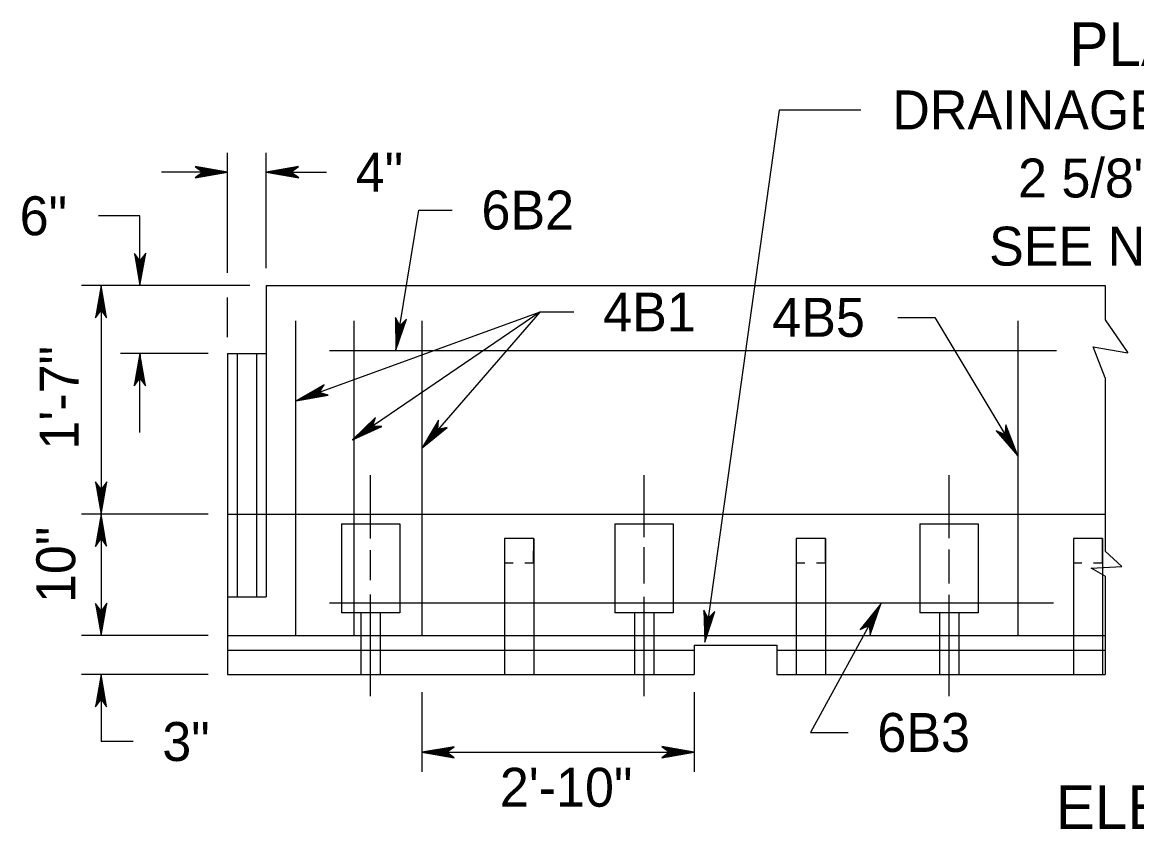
# Model space of a CAD drawing. Extents: x 499883 to 500983, y 499104 to 499764.
# Drawn here: x 500279.7 to 500394.2, y 499232.3 to 499315.2 of the extents above; entities that cross this region are included whole.
import ezdxf

# ---------------------------------------------------------------- set-up
doc = ezdxf.new("R2010")
doc.units = 0
for name, color, linetype in [('1', 7, 'Continuous'), ('24', 7, 'Continuous'), ('3', 7, 'Continuous'), ('5', 7, 'Continuous')]:
    doc.layers.add(name, color=color, linetype=linetype)

msp = doc.modelspace()

# ---------------------------------------------------------------- linework, layer by layer
at = {"layer": '1'}
for p, q in [((500315.49, 499262.18), (500315.49, 499268.7)), ((500343.61, 499262.32), (500343.61, 499268.7)), ((500374.95, 499262.22), (500374.95, 499268.7)), ((500315.49, 499257.89), (500315.49, 499260.99)), ((500343.61, 499257.57), (500343.61, 499261.31)), ((500374.95, 499257.57), (500374.95, 499261.04)), ((500315.49, 499245.98), (500315.49, 499256.43)), ((500343.61, 499245.98), (500343.61, 499256.2)), ((500374.95, 499245.98), (500374.95, 499256.39))]:
    msp.add_line(p, q, dxfattribs=at)
at = {"layer": '24'}
for points in [[(500318.08, 499281.55), (500320.45, 499295.94), (500323.89, 499295.94)], [(500318.08, 499281.55), (500319.2, 499284.73), (500318.49, 499284.05), (500318.05, 499284.91), (500318.08, 499281.55), (500318.11, 499281.77), (500319.14, 499284.65), (500318.48, 499283.99), (500318.07, 499284.77), (500318.12, 499281.89), (500318.16, 499281.99), (500319.03, 499284.46), (500318.47, 499283.97), (500318.12, 499284.63), (500318.16, 499282.04), (500318.17, 499282.16), (500318.93, 499284.31), (500318.48, 499283.95), (500318.15, 499284.45), (500318.22, 499282.47), (500318.25, 499282.66), (500318.82, 499284.16), (500318.48, 499283.91), (500318.21, 499284.29), (500318.27, 499282.69), (500318.31, 499282.86), (500318.7, 499284), (500318.44, 499283.81), (500318.25, 499284.09), (500318.32, 499283.02), (500318.37, 499283.19), (500318.62, 499283.87), (500318.44, 499283.78), (500318.3, 499284), (500318.37, 499283.28), (500318.55, 499283.72), (500318.41, 499283.67), (500318.32, 499283.89), (500318.37, 499283.39), (500318.49, 499283.68), (500318.37, 499283.57), (500318.34, 499283.73), (500318.41, 499283.57), (500318.44, 499283.64)], [(500307.86, 499276.34), (500311.14, 499276.92), (500310.2, 499277.2), (500310.73, 499277.99), (500307.86, 499276.34), (500308.06, 499276.42), (500311.03, 499276.93), (500310.14, 499277.18), (500310.62, 499277.91), (500308.17, 499276.47), (500308.28, 499276.49), (500310.82, 499276.94), (500310.13, 499277.18), (500310.53, 499277.79), (500308.33, 499276.51), (500308.42, 499276.56), (500310.64, 499276.95), (500310.11, 499277.16), (500310.38, 499277.69), (500308.72, 499276.67), (500308.89, 499276.74), (500310.46, 499276.97), (500310.08, 499277.14), (500310.27, 499277.56), (500308.93, 499276.73), (500309.1, 499276.78), (500310.26, 499276.99), (500309.97, 499277.13), (500310.13, 499277.42), (500309.24, 499276.85), (500309.4, 499276.89), (500310.11, 499277), (500309.95, 499277.11), (500310.07, 499277.34), (500309.48, 499276.93), (500309.95, 499276.99), (500309.84, 499277.08), (500309.99, 499277.27), (500309.58, 499276.99), (500309.89, 499277.02), (500309.74, 499277.07), (500309.85, 499277.17), (500309.75, 499277.04), (500309.83, 499277.05)], [(500313.63, 499272.31), (500316.66, 499273.68), (500315.69, 499273.71), (500316, 499274.62), (500313.63, 499272.31), (500313.81, 499272.44), (500316.56, 499273.66), (500315.64, 499273.69), (500315.92, 499274.5), (500313.9, 499272.51), (500314, 499272.56), (500316.35, 499273.62), (500315.62, 499273.68), (500315.86, 499274.37), (500314.04, 499272.59), (500314.12, 499272.66), (500316.18, 499273.58), (500315.61, 499273.66), (500315.75, 499274.24), (500314.38, 499272.84), (500314.54, 499272.94), (500316, 499273.56), (500315.58, 499273.63), (500315.67, 499274.08), (500314.57, 499272.95), (500314.72, 499273.04), (500315.8, 499273.53), (500315.49, 499273.59), (500315.56, 499273.92), (500314.85, 499273.14), (500314.99, 499273.22), (500315.65, 499273.5), (500315.47, 499273.57), (500315.52, 499273.82), (500315.06, 499273.28), (500315.49, 499273.45), (500315.37, 499273.51), (500315.46, 499273.73), (500315.14, 499273.36), (500315.43, 499273.47), (500315.27, 499273.48), (500315.36, 499273.61), (500315.29, 499273.45), (500315.36, 499273.48)], [(500313.63, 499272.31), (500316.66, 499273.68), (500315.69, 499273.71), (500316, 499274.62), (500313.63, 499272.31), (500313.81, 499272.44), (500316.56, 499273.66), (500315.64, 499273.69), (500315.92, 499274.5), (500313.9, 499272.51), (500314, 499272.56), (500316.35, 499273.62), (500315.62, 499273.68), (500315.86, 499274.37), (500314.04, 499272.59), (500314.12, 499272.66), (500316.18, 499273.58), (500315.61, 499273.66), (500315.75, 499274.24), (500314.38, 499272.84), (500314.54, 499272.94), (500316, 499273.56), (500315.58, 499273.63), (500315.67, 499274.08), (500314.57, 499272.95), (500314.72, 499273.04), (500315.8, 499273.53), (500315.49, 499273.59), (500315.56, 499273.92), (500314.85, 499273.14), (500314.99, 499273.22), (500315.65, 499273.5), (500315.47, 499273.57), (500315.52, 499273.82), (500315.06, 499273.28), (500315.49, 499273.45), (500315.37, 499273.51), (500315.46, 499273.73), (500315.14, 499273.36), (500315.43, 499273.47), (500315.27, 499273.48), (500315.36, 499273.61), (500315.29, 499273.45), (500315.36, 499273.48)], [(500320.78, 499271.5), (500323.36, 499273.59), (500322.41, 499273.38), (500322.49, 499274.33), (500320.78, 499271.5), (500320.92, 499271.67), (500323.27, 499273.55), (500322.37, 499273.34), (500322.43, 499274.21), (500320.99, 499271.77), (500321.07, 499271.84), (500323.08, 499273.46), (500322.36, 499273.33), (500322.41, 499274.06), (500321.1, 499271.87), (500321.16, 499271.97), (500322.92, 499273.38), (500322.35, 499273.31), (500322.34, 499273.9), (500321.37, 499272.21), (500321.49, 499272.35), (500322.75, 499273.31), (500322.33, 499273.27), (500322.3, 499273.73), (500321.53, 499272.36), (500321.65, 499272.49), (500322.56, 499273.24), (500322.25, 499273.22), (500322.24, 499273.55), (500321.74, 499272.61), (500321.87, 499272.73), (500322.43, 499273.17), (500322.23, 499273.19), (500322.23, 499273.44), (500321.91, 499272.8), (500322.29, 499273.08), (500322.15, 499273.11), (500322.19, 499273.34), (500321.97, 499272.9), (500322.23, 499273.08), (500322.07, 499273.05), (500322.12, 499273.2), (500322.09, 499273.03), (500322.16, 499273.07)], [(500382, 499270.68), (500380.79, 499273.86), (500380.69, 499272.87), (500379.79, 499273.24), (500382, 499270.68), (500381.88, 499270.87), (500380.8, 499273.75), (500380.72, 499272.81), (500379.9, 499273.15), (500381.81, 499270.96), (500381.77, 499271.07), (500380.83, 499273.53), (500380.73, 499272.79), (500380.03, 499273.07), (500381.74, 499271.11), (500381.67, 499271.2), (500380.86, 499273.36), (500380.75, 499272.78), (500380.17, 499272.95), (500381.51, 499271.48), (500381.41, 499271.64), (500380.87, 499273.17), (500380.77, 499272.75), (500380.32, 499272.87), (500381.41, 499271.68), (500381.32, 499271.83), (500380.89, 499272.97), (500380.8, 499272.65), (500380.48, 499272.75), (500381.23, 499271.97), (500381.16, 499272.12), (500380.91, 499272.81), (500380.83, 499272.63), (500380.58, 499272.7), (500381.1, 499272.19), (500380.95, 499272.65), (500380.88, 499272.53), (500380.66, 499272.64), (500381.02, 499272.28), (500380.93, 499272.59), (500380.91, 499272.42), (500380.78, 499272.52), (500380.94, 499272.44), (500380.92, 499272.52)], [(500367.93, 499255.48), (500360.71, 499242.25), (500364.58, 499242.25)], [(500367.93, 499255.48), (500365.82, 499252.84), (500366.72, 499253.26), (500366.85, 499252.3), (500367.93, 499255.48), (500367.83, 499255.28), (500365.9, 499252.9), (500366.75, 499253.31), (500366.88, 499252.44), (500367.78, 499255.17), (500367.71, 499255.08), (500366.08, 499253.04), (500366.76, 499253.32), (500366.87, 499252.59), (500367.69, 499255.04), (500367.65, 499254.93), (500366.21, 499253.15), (500366.77, 499253.35), (500366.91, 499252.76), (500367.5, 499254.65), (500367.41, 499254.49), (500366.37, 499253.26), (500366.78, 499253.38), (500366.91, 499252.94), (500367.38, 499254.47), (500367.28, 499254.31), (500366.54, 499253.37), (500366.85, 499253.46), (500366.93, 499253.13), (500367.21, 499254.17), (500367.12, 499254.03), (500366.66, 499253.47), (500366.85, 499253.49), (500366.92, 499253.24), (500367.09, 499253.94), (500366.77, 499253.59), (500366.92, 499253.59), (500366.93, 499253.35), (500367.05, 499253.83), (500366.84, 499253.6), (500366.99, 499253.67), (500366.97, 499253.51), (500366.96, 499253.68), (500366.91, 499253.62)], [(500349.85, 499251.52), (500350.88, 499254.68), (500350.2, 499253.98), (500349.74, 499254.82), (500349.85, 499251.52), (500349.87, 499251.73), (500350.82, 499254.59), (500350.18, 499253.92), (500349.76, 499254.68), (500349.88, 499251.85), (500349.91, 499251.96), (500350.71, 499254.41), (500350.18, 499253.91), (500349.82, 499254.55), (500349.92, 499252), (500349.92, 499252.11), (500350.62, 499254.26), (500350.18, 499253.88), (500349.85, 499254.38), (500349.96, 499252.43), (500349.99, 499252.61), (500350.52, 499254.11), (500350.19, 499253.85), (500349.91, 499254.22), (500350.01, 499252.64), (500350.04, 499252.81), (500350.4, 499253.94), (500350.15, 499253.75), (500349.96, 499254.02), (500350.05, 499252.97), (500350.09, 499253.13), (500350.32, 499253.81), (500350.15, 499253.72), (500350, 499253.93), (500350.09, 499253.22), (500350.26, 499253.66), (500350.13, 499253.61), (500350.03, 499253.83), (500350.09, 499253.34), (500350.2, 499253.62), (500350.09, 499253.51), (500350.05, 499253.67), (500350.12, 499253.51), (500350.15, 499253.58)], [(500320.76, 499240.21), (500324.09, 499239.63), (500323.29, 499240.21), (500324.07, 499240.79), (500320.76, 499240.21), (500320.99, 499240.22), (500324, 499239.67), (500323.23, 499240.22), (500323.94, 499240.75), (500321.1, 499240.23), (500321.22, 499240.21), (500323.79, 499239.76), (500323.22, 499240.22), (500323.81, 499240.67), (500321.27, 499240.21), (500321.38, 499240.23), (500323.63, 499239.82), (500323.19, 499240.21), (500323.64, 499240.62), (500321.7, 499240.23), (500321.88, 499240.23), (500323.46, 499239.91), (500323.16, 499240.2), (500323.49, 499240.53), (500321.92, 499240.21), (500322.1, 499240.2), (500323.28, 499240), (500323.05, 499240.23), (500323.3, 499240.46), (500322.26, 499240.21), (500322.43, 499240.2), (500323.14, 499240.06), (500323.02, 499240.22), (500323.22, 499240.4), (500322.51, 499240.21), (500322.98, 499240.1), (500322.91, 499240.23), (500323.11, 499240.36), (500322.63, 499240.23), (500322.93, 499240.15), (500322.81, 499240.25), (500322.95, 499240.31), (500322.81, 499240.22), (500322.88, 499240.2)], [(500348.75, 499240.21), (500345.43, 499240.8), (500346.22, 499240.21), (500345.44, 499239.64), (500348.75, 499240.21), (500348.53, 499240.21), (500345.52, 499240.76), (500346.28, 499240.21), (500345.58, 499239.68), (500348.41, 499240.2), (500348.3, 499240.21), (500345.72, 499240.67), (500346.3, 499240.21), (500345.7, 499239.76), (500348.25, 499240.21), (500348.14, 499240.2), (500345.88, 499240.6), (500346.32, 499240.21), (500345.88, 499239.81), (500347.82, 499240.2), (500347.63, 499240.2), (500346.05, 499240.52), (500346.36, 499240.22), (500346.03, 499239.89), (500347.6, 499240.21), (500347.42, 499240.22), (500346.23, 499240.43), (500346.46, 499240.2), (500346.21, 499239.97), (500347.26, 499240.21), (500347.09, 499240.23), (500346.38, 499240.37), (500346.49, 499240.21), (500346.3, 499240.03), (500347, 499240.21), (500346.54, 499240.32), (500346.6, 499240.2), (500346.4, 499240.07), (500346.88, 499240.2), (500346.58, 499240.27), (500346.71, 499240.17), (500346.56, 499240.11), (500346.71, 499240.21), (500346.63, 499240.22)]]:
    msp.add_lwpolyline(points, dxfattribs=at)
at = {"layer": '3'}
for points in [[(500329.26, 499262.2), (500329.26, 499259.68), (500330.14, 499259.69)], [(500331.34, 499259.69), (500332.25, 499259.69), (500332.26, 499262.2), (500329.26, 499262.2)], [(500359.24, 499262.2), (500359.24, 499259.68), (500360.12, 499259.69)], [(500361.32, 499259.69), (500362.24, 499259.69), (500362.24, 499262.2), (500359.24, 499262.2)], [(500387.72, 499262.2), (500387.72, 499259.68), (500388.6, 499259.69)], [(500389.8, 499259.69), (500390.71, 499259.69), (500390.72, 499262.2), (500387.72, 499262.2)]]:
    msp.add_lwpolyline(points, dxfattribs=at)
at = {"layer": '5'}
for p, q in [((500300.79, 499289.48), (500300.79, 499301.83)), ((500304.78, 499289.95), (500304.78, 499301.83)), ((500300.79, 499299.83), (500294.02, 499299.83)), ((500304.78, 499299.83), (500310.97, 499299.83)), ((500291.79, 499295.35), (500287.54, 499295.35)), ((500291.79, 499288.18), (500291.79, 499295.35)), ((500303.09, 499288.18), (500285.8, 499288.18)), ((500287.8, 499288.18), (500287.8, 499264.7)), ((500304.78, 499288.18), (500391, 499288.18)), ((500304.78, 499288.18), (500304.78, 499281.18)), ((500391, 499288.18), (500391, 499284.64)), ((500300.79, 499282.88), (500300.79, 499286.94)), ((500332.9, 499285.46), (500313.63, 499272.31)), ((500332.9, 499285.46), (500320.78, 499271.5)), ((500307.77, 499284.56), (500307.77, 499252.2)), ((500313.77, 499284.56), (500313.77, 499252.2)), ((500320.76, 499284.56), (500320.76, 499252.2)), ((500382, 499284.56), (500382, 499252.2)), ((500391, 499284.64), (500393.31, 499281.27)), ((500391, 499278.7), (500389.75, 499281.87)), ((500389.75, 499281.87), (500393.31, 499281.27)), ((500298.81, 499281.18), (500289.79, 499281.18)), ((500291.79, 499273.09), (500291.79, 499281.18)), ((500300.79, 499281.18), (500300.79, 499248.21)), ((500300.79, 499281.18), (500304.78, 499281.18)), ((500301.79, 499281.18), (500301.79, 499256.2)), ((500303.78, 499281.18), (500303.78, 499256.2)), ((500304.78, 499281.18), (500304.78, 499256.2)), ((500311.26, 499281.5), (500386, 499281.5)), ((500391, 499278.7), (500391, 499260.89)), ((500298.81, 499264.7), (500285.8, 499264.7)), ((500287.8, 499264.7), (500287.8, 499252.2)), ((500300.79, 499264.7), (500391, 499264.7)), ((500312.49, 499263.7), (500312.49, 499254.56)), ((500312.49, 499263.7), (500318.49, 499263.7)), ((500318.49, 499263.7), (500318.49, 499254.56)), ((500340.61, 499263.7), (500340.61, 499254.56)), ((500340.61, 499263.7), (500346.61, 499263.7)), ((500346.61, 499263.7), (500346.61, 499254.56)), ((500371.95, 499263.7), (500371.95, 499254.56)), ((500371.95, 499263.7), (500377.94, 499263.7)), ((500377.94, 499263.7), (500377.94, 499254.56)), ((500329.26, 499262.2), (500329.26, 499248.21)), ((500332.26, 499262.2), (500332.26, 499248.21)), ((500359.24, 499262.2), (500359.24, 499248.21)), ((500362.24, 499262.2), (500362.24, 499248.21)), ((500387.72, 499262.2), (500387.72, 499248.21)), ((500390.72, 499262.2), (500390.72, 499248.21)), ((500391, 499260.89), (500392.72, 499259.31)), ((500389.55, 499259.14), (500392.72, 499259.31)), ((500391, 499258.32), (500389.55, 499259.14)), ((500391, 499258.32), (500391, 499248.21)), ((500300.79, 499256.2), (500304.78, 499256.2)), ((500311.26, 499255.56), (500385.67, 499255.56)), ((500318.49, 499254.56), (500312.49, 499254.56)), ((500314.49, 499254.56), (500314.49, 499248.21)), ((500316.49, 499254.56), (500316.49, 499248.21)), ((500346.61, 499254.56), (500340.61, 499254.56)), ((500342.61, 499254.56), (500342.61, 499248.21)), ((500344.61, 499254.56), (500344.61, 499248.21)), ((500377.94, 499254.56), (500371.95, 499254.56)), ((500373.95, 499254.56), (500373.95, 499248.21)), ((500375.94, 499254.56), (500375.94, 499248.21)), ((500298.81, 499252.2), (500285.8, 499252.2)), ((500300.79, 499252.2), (500391, 499252.2)), ((500300.79, 499250.71), (500348.75, 499250.71)), ((500348.75, 499251.21), (500357.24, 499251.21)), ((500348.75, 499251.21), (500348.75, 499248.21)), ((500357.24, 499251.21), (500357.24, 499248.21)), ((500357.24, 499250.71), (500391, 499250.71)), ((500298.81, 499248.21), (500285.8, 499248.21)), ((500287.8, 499248.21), (500287.8, 499241.32)), ((500300.79, 499248.21), (500348.75, 499248.21)), ((500357.24, 499248.21), (500391, 499248.21)), ((500320.76, 499246.4), (500320.76, 499238.22)), ((500348.75, 499246.4), (500348.75, 499238.22)), ((500291.09, 499241.32), (500287.8, 499241.32)), ((500320.76, 499240.21), (500348.75, 499240.21))]:
    msp.add_line(p, q, dxfattribs=at)
for points in [[(500365.88, 499306.22), (500357.5, 499306.22), (500349.85, 499251.52)], [(500300.79, 499299.83), (500297.46, 499300.42), (500298.26, 499299.83), (500297.48, 499299.26), (500300.79, 499299.83), (500300.57, 499299.83), (500297.56, 499300.38), (500298.32, 499299.83), (500297.61, 499299.3), (500300.45, 499299.82), (500300.34, 499299.83), (500297.76, 499300.29), (500298.34, 499299.83), (500297.74, 499299.38), (500300.29, 499299.83), (500300.18, 499299.82), (500297.92, 499300.22), (500298.36, 499299.83), (500297.91, 499299.43), (500299.85, 499299.82), (500299.67, 499299.82), (500298.09, 499300.14), (500298.4, 499299.84), (500298.06, 499299.51), (500299.63, 499299.83), (500299.46, 499299.84), (500298.27, 499300.05), (500298.5, 499299.82), (500298.25, 499299.59), (500299.29, 499299.83), (500299.12, 499299.85), (500298.41, 499299.99), (500298.53, 499299.83), (500298.34, 499299.65), (500299.04, 499299.83), (500298.57, 499299.95), (500298.64, 499299.82), (500298.44, 499299.69), (500298.92, 499299.82), (500298.62, 499299.89), (500298.74, 499299.79), (500298.6, 499299.73), (500298.74, 499299.83), (500298.67, 499299.84)], [(500304.78, 499299.83), (500308.11, 499299.25), (500307.31, 499299.83), (500308.09, 499300.41), (500304.78, 499299.83), (500305, 499299.84), (500308.01, 499299.29), (500307.25, 499299.84), (500307.96, 499300.37), (500305.12, 499299.85), (500305.23, 499299.83), (500307.81, 499299.38), (500307.23, 499299.84), (500307.83, 499300.29), (500305.28, 499299.83), (500305.4, 499299.85), (500307.65, 499299.44), (500307.21, 499299.83), (500307.66, 499300.24), (500305.72, 499299.85), (500305.9, 499299.85), (500307.48, 499299.53), (500307.18, 499299.83), (500307.51, 499300.16), (500305.94, 499299.83), (500306.11, 499299.82), (500307.3, 499299.62), (500307.07, 499299.85), (500307.32, 499300.08), (500306.28, 499299.83), (500306.45, 499299.82), (500307.16, 499299.68), (500307.04, 499299.84), (500307.23, 499300.02), (500306.53, 499299.83), (500307, 499299.72), (500306.93, 499299.85), (500307.13, 499299.98), (500306.65, 499299.85), (500306.95, 499299.78), (500306.83, 499299.88), (500306.97, 499299.94), (500306.83, 499299.84), (500306.9, 499299.83)], [(500291.79, 499288.18), (500292.38, 499291.5), (500291.79, 499290.71), (500291.22, 499291.48), (500291.79, 499288.18), (500291.79, 499288.4), (500292.34, 499291.41), (500291.79, 499290.65), (500291.26, 499291.35), (500291.78, 499288.52), (500291.79, 499288.63), (500292.25, 499291.21), (500291.79, 499290.63), (500291.34, 499291.22), (500291.79, 499288.68), (500291.78, 499288.79), (500292.18, 499291.04), (500291.79, 499290.6), (500291.39, 499291.05), (500291.78, 499289.11), (500291.78, 499289.3), (500292.1, 499290.88), (500291.8, 499290.57), (500291.47, 499290.9), (500291.79, 499289.33), (500291.8, 499289.51), (500292.01, 499290.7), (500291.78, 499290.47), (500291.55, 499290.71), (500291.79, 499289.67), (500291.81, 499289.84), (500291.95, 499290.55), (500291.79, 499290.43), (500291.61, 499290.63), (500291.79, 499289.93), (500291.9, 499290.39), (500291.78, 499290.32), (500291.65, 499290.53), (500291.78, 499290.04), (500291.85, 499290.35), (500291.75, 499290.22), (500291.69, 499290.37), (500291.79, 499290.22), (500291.8, 499290.3)], [(500287.8, 499288.18), (500287.21, 499284.85), (500287.8, 499285.65), (500288.37, 499284.87), (500287.8, 499288.18), (500287.8, 499287.96), (500287.25, 499284.95), (500287.8, 499285.71), (500288.33, 499285), (500287.81, 499287.84), (500287.8, 499287.73), (500287.34, 499285.15), (500287.8, 499285.73), (500288.25, 499285.13), (500287.8, 499287.68), (500287.81, 499287.57), (500287.41, 499285.31), (500287.8, 499285.75), (500288.2, 499285.3), (500287.81, 499287.24), (500287.81, 499287.06), (500287.49, 499285.48), (500287.79, 499285.79), (500288.12, 499285.46), (500287.8, 499287.02), (500287.79, 499286.85), (500287.58, 499285.66), (500287.81, 499285.89), (500288.04, 499285.64), (500287.8, 499286.68), (500287.78, 499286.52), (500287.64, 499285.8), (500287.8, 499285.92), (500287.98, 499285.73), (500287.8, 499286.43), (500287.69, 499285.96), (500287.81, 499286.03), (500287.94, 499285.83), (500287.81, 499286.31), (500287.74, 499286.01), (500287.84, 499286.13), (500287.9, 499285.99), (500287.8, 499286.13), (500287.79, 499286.06)], [(500336.4, 499285.46), (500332.9, 499285.46), (500307.86, 499276.34)], [(500369.69, 499284.91), (500373.5, 499284.89), (500382, 499270.68)], [(500291.79, 499281.18), (500291.21, 499277.86), (500291.79, 499278.65), (500292.37, 499277.88), (500291.79, 499281.18), (500291.8, 499280.96), (500291.25, 499277.95), (500291.8, 499278.72), (500292.33, 499278.01), (500291.81, 499280.84), (500291.79, 499280.73), (500291.34, 499278.15), (500291.8, 499278.73), (500292.25, 499278.14), (500291.79, 499280.68), (500291.81, 499280.57), (500291.4, 499278.32), (500291.79, 499278.76), (500292.2, 499278.31), (500291.81, 499280.25), (500291.81, 499280.06), (500291.49, 499278.48), (500291.78, 499278.79), (500292.11, 499278.46), (500291.79, 499280.03), (500291.78, 499279.85), (500291.58, 499278.66), (500291.81, 499278.89), (500292.04, 499278.65), (500291.79, 499279.69), (500291.78, 499279.52), (500291.64, 499278.81), (500291.8, 499278.93), (500291.98, 499278.73), (500291.79, 499279.43), (500291.68, 499278.97), (500291.81, 499279.04), (500291.94, 499278.83), (500291.81, 499279.32), (500291.73, 499279.01), (500291.83, 499279.14), (500291.89, 499278.99), (500291.8, 499279.14), (500291.78, 499279.06)], [(500287.8, 499264.7), (500288.38, 499268.02), (500287.8, 499267.22), (500287.22, 499268), (500287.8, 499264.7), (500287.79, 499264.92), (500288.34, 499267.93), (500287.79, 499267.16), (500287.26, 499267.87), (500287.78, 499265.04), (500287.8, 499265.15), (500288.25, 499267.72), (500287.79, 499267.15), (500287.34, 499267.74), (500287.8, 499265.2), (500287.78, 499265.31), (500288.19, 499267.56), (500287.8, 499267.12), (500287.39, 499267.57), (500287.78, 499265.63), (500287.78, 499265.82), (500288.1, 499267.39), (500287.81, 499267.09), (500287.48, 499267.42), (500287.8, 499265.85), (500287.81, 499266.03), (500288.01, 499267.21), (500287.78, 499266.98), (500287.55, 499267.23), (500287.8, 499266.19), (500287.81, 499266.36), (500287.95, 499267.07), (500287.79, 499266.95), (500287.61, 499267.15), (500287.8, 499266.44), (500287.91, 499266.91), (500287.78, 499266.84), (500287.65, 499267.05), (500287.78, 499266.56), (500287.86, 499266.87), (500287.76, 499266.74), (500287.7, 499266.88), (500287.79, 499266.74), (500287.81, 499266.82)], [(500287.8, 499264.7), (500287.21, 499261.37), (500287.8, 499262.17), (500288.37, 499261.39), (500287.8, 499264.7), (500287.8, 499264.47), (500287.25, 499261.46), (500287.8, 499262.23), (500288.33, 499261.52), (500287.81, 499264.36), (500287.8, 499264.24), (500287.34, 499261.67), (500287.8, 499262.24), (500288.25, 499261.65), (500287.8, 499264.19), (500287.81, 499264.08), (500287.41, 499261.83), (500287.8, 499262.27), (500288.2, 499261.82), (500287.81, 499263.76), (500287.81, 499263.57), (500287.49, 499262), (500287.79, 499262.3), (500288.12, 499261.97), (500287.8, 499263.54), (500287.79, 499263.36), (500287.58, 499262.18), (500287.81, 499262.41), (500288.04, 499262.16), (500287.8, 499263.2), (500287.78, 499263.03), (500287.64, 499262.32), (500287.8, 499262.44), (500287.98, 499262.24), (500287.8, 499262.95), (500287.69, 499262.48), (500287.81, 499262.55), (500287.94, 499262.34), (500287.81, 499262.83), (500287.74, 499262.53), (500287.84, 499262.65), (500287.9, 499262.51), (500287.8, 499262.65), (500287.79, 499262.58)], [(500287.8, 499252.2), (500288.38, 499255.53), (500287.8, 499254.73), (500287.22, 499255.51), (500287.8, 499252.2), (500287.79, 499252.43), (500288.34, 499255.44), (500287.79, 499254.67), (500287.26, 499255.38), (500287.78, 499252.54), (500287.8, 499252.66), (500288.25, 499255.23), (500287.79, 499254.66), (500287.34, 499255.25), (500287.8, 499252.71), (500287.78, 499252.82), (500288.19, 499255.07), (500287.8, 499254.63), (500287.39, 499255.08), (500287.78, 499253.14), (500287.78, 499253.32), (500288.1, 499254.9), (500287.81, 499254.6), (500287.48, 499254.93), (500287.8, 499253.36), (500287.81, 499253.54), (500288.01, 499254.72), (500287.78, 499254.49), (500287.55, 499254.74), (500287.8, 499253.7), (500287.81, 499253.87), (500287.95, 499254.58), (500287.79, 499254.46), (500287.61, 499254.66), (500287.8, 499253.95), (500287.91, 499254.42), (500287.78, 499254.35), (500287.65, 499254.55), (500287.78, 499254.07), (500287.86, 499254.37), (500287.76, 499254.25), (500287.7, 499254.39), (500287.79, 499254.25), (500287.81, 499254.32)], [(500287.8, 499248.21), (500287.21, 499244.88), (500287.8, 499245.68), (500288.37, 499244.9), (500287.8, 499248.21), (500287.8, 499247.99), (500287.25, 499244.98), (500287.8, 499245.74), (500288.33, 499245.04), (500287.81, 499247.87), (500287.8, 499247.76), (500287.34, 499245.18), (500287.8, 499245.76), (500288.25, 499245.16), (500287.8, 499247.71), (500287.81, 499247.6), (500287.41, 499245.34), (500287.8, 499245.78), (500288.2, 499245.33), (500287.81, 499247.28), (500287.81, 499247.09), (500287.49, 499245.51), (500287.79, 499245.82), (500288.12, 499245.49), (500287.8, 499247.05), (500287.79, 499246.88), (500287.58, 499245.69), (500287.81, 499245.92), (500288.04, 499245.67), (500287.8, 499246.71), (500287.78, 499246.55), (500287.64, 499245.83), (500287.8, 499245.95), (500287.98, 499245.76), (500287.8, 499246.46), (500287.69, 499245.99), (500287.81, 499246.06), (500287.94, 499245.86), (500287.81, 499246.34), (500287.74, 499246.04), (500287.84, 499246.17), (500287.9, 499246.02), (500287.8, 499246.16), (500287.79, 499246.09)]]:
    msp.add_lwpolyline(points, dxfattribs=at)

# ---------------------------------------------------------------- texts
for s, height, p in [('PLAN', 4.5, (500387.31, 499310.74)), ('DRAINAGE POCKET', 4, (500369.11, 499304.23)), ('4"', 4, (500313.97, 499297.83)), ('2 5/8" x 5 1/2"', 4, (500382.04, 499297.23)), ('6B2', 4, (500326.89, 499293.94)), ('6"', 4, (500279.43, 499293.35)), ('SEE NOTE 9', 4, (500379.06, 499290.23)), ('4B1', 4, (500339.4, 499283.46)), ('4B5', 4, (500356.78, 499282.91)), ('6B3', 4, (500367.58, 499240.25)), ('3"', 4, (500294.09, 499239.32)), ('2\'-10"', 4, (500328.78, 499234.62)), ('ELEVATION', 4.5, (500385.92, 499232.32))]:
    msp.add_text(s, height=height, dxfattribs=at).set_placement(p)
for s, p in [('1\'-7"', (500285.49, 499271.32)), ('10"', (500285.14, 499255.55))]:
    msp.add_text(s, height=4, rotation=90, dxfattribs=at).set_placement(p)

doc.saveas('drawing.dxf')
